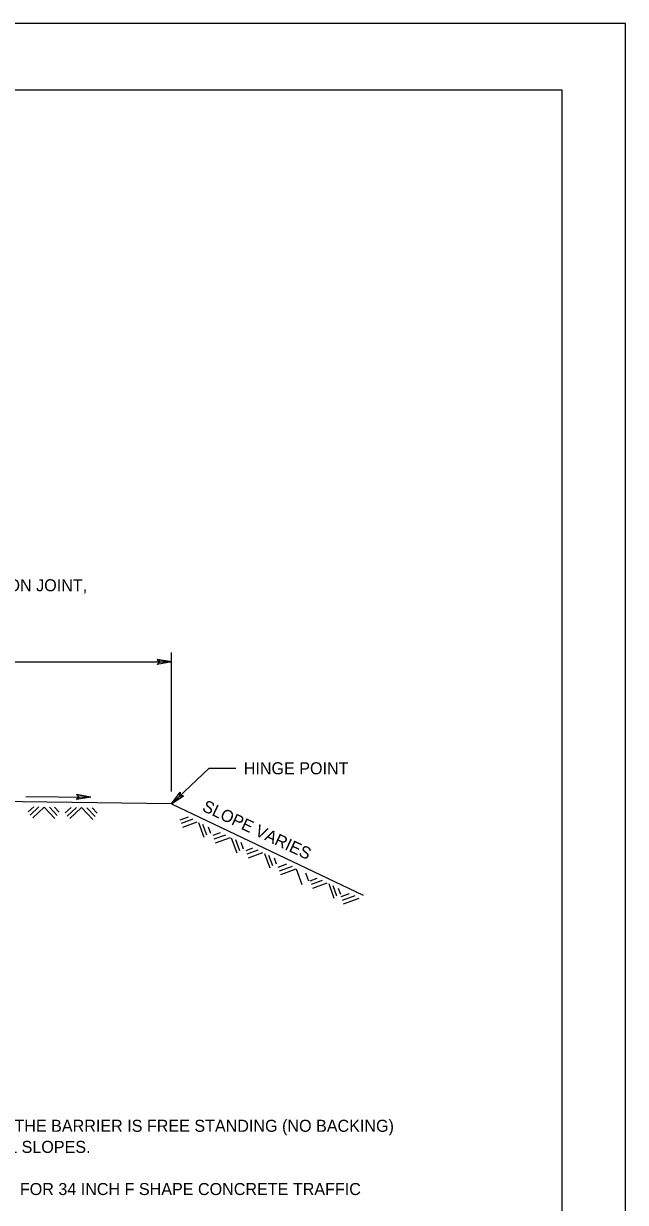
# Model space of a CAD drawing. Extents: x -32.9 to -15.8, y -6.5 to 4.5.
# Drawn here: x -18.82 to -15.82, y -1.37 to 4.5 of the extents above; entities that cross this region are included whole.
import ezdxf

# ---------------------------------------------------------------- set-up
doc = ezdxf.new("R2010")
doc.units = 0
for name, color, linetype in [('BORD-LINE', 7, 'Continuous'), ('DETL-DIMS', 7, 'Continuous'), ('Level 10', 7, 'Continuous'), ('Level 12', 7, 'Continuous'), ('Level 6', 7, 'Continuous'), ('SECT-GRND_P', 7, 'Continuous'), ('USER-CLIP', 7, 'Continuous')]:
    doc.layers.add(name, color=color, linetype=linetype)

msp = doc.modelspace()

# ---------------------------------------------------------------- linework, layer by layer
at = {"layer": 'BORD-LINE'}
msp.add_lwpolyline([(-23.5151, 4.1733), (-16.1409, 4.1733), (-16.1409, -6.1798), (-23.5151, -6.1798)], close=True, dxfattribs=at)
at = {"layer": 'DETL-DIMS'}
for p, q in [((-18.0854, 1.3241), (-18.1569, 1.3366)), ((-18.1569, 1.3366), (-18.1434, 1.3241)), ((-18.0854, 1.3241), (-18.1569, 1.3114)), ((-18.1434, 1.3241), (-18.1569, 1.3114)), ((-18.5445, 0.6509), (-18.5582, 0.6383)), ((-18.4865, 0.6502), (-18.5582, 0.6383)), ((-18.4865, 0.6502), (-18.5579, 0.6635)), ((-18.5579, 0.6635), (-18.5445, 0.6509)), ((-18.0854, 0.6164), (-18.0422, 0.6748)), ((-18.0854, 0.6164), (-18.0249, 0.6565)), ((-18.0433, 0.6563), (-18.0422, 0.6748)), ((-18.0249, 0.6565), (-18.0433, 0.6563))]:
    msp.add_line(p, q, dxfattribs=at)
for points in [[(-18.1569, 1.3366), (-18.0854, 1.3241), (-18.1569, 1.3114), (-18.1434, 1.3241)], [(-18.5579, 0.6635), (-18.4865, 0.6502), (-18.5582, 0.6383), (-18.5445, 0.6509)], [(-18.0249, 0.6565), (-18.0854, 0.6164), (-18.0422, 0.6748), (-18.0433, 0.6563)]]:
    msp.add_lwpolyline(points, close=True, dxfattribs=at)
at = {"layer": 'Level 10'}
for p, q in [((-18.0854, 0.6776), (-18.0854, 1.3714)), ((-20.0854, 1.3241), (-18.0854, 1.3241)), ((-17.8982, 0.794), (-18.0854, 0.6164)), ((-17.8982, 0.794), (-17.7654, 0.794)), ((-18.8108, 0.6539), (-18.4865, 0.6502))]:
    msp.add_line(p, q, dxfattribs=at)
at = {"layer": 'Level 6'}
for p, q in [((-18.7986, 0.5763), (-18.7716, 0.6016)), ((-18.7456, 0.6012), (-18.7886, 0.561)), ((-18.776, 0.548), (-18.7196, 0.6008)), ((-18.7196, 0.6008), (-18.6665, 0.5444)), ((-18.6548, 0.5594), (-18.6936, 0.6004)), ((-18.6676, 0.6001), (-18.6443, 0.5752)), ((-18.6143, 0.5715), (-18.5849, 0.5989)), ((-18.5589, 0.5985), (-18.6044, 0.556)), ((-18.5917, 0.5432), (-18.5329, 0.5981)), ((-18.5329, 0.5981), (-18.4778, 0.5394)), ((-18.466, 0.5544), (-18.5069, 0.5978)), ((-18.4809, 0.5974), (-18.4553, 0.5702)), ((-18.0415, 0.5379), (-18.0004, 0.5529)), ((-17.9792, 0.5398), (-18.037, 0.5188)), ((-18.0295, 0.5009), (-17.9567, 0.5274)), ((-17.95, 0.5244), (-17.9235, 0.4513)), ((-17.9089, 0.4609), (-17.9284, 0.5141)), ((-17.903, 0.5023), (-17.8914, 0.4701)), ((-17.8784, 0.4601), (-17.8419, 0.4734)), ((-17.8165, 0.4616), (-17.8739, 0.4408)), ((-17.8664, 0.4231), (-17.792, 0.4499)), ((-17.7875, 0.4478), (-17.7604, 0.3734)), ((-17.7455, 0.3829), (-17.7655, 0.4374)), ((-17.7404, 0.4256), (-17.728, 0.3921)), ((-17.7137, 0.3851), (-17.68, 0.3973)), ((-17.655, 0.3854), (-17.7092, 0.3658)), ((-17.7017, 0.3481), (-17.6304, 0.3739)), ((-17.6217, 0.3698), (-17.5957, 0.2984)), ((-17.581, 0.3079), (-17.5999, 0.3596)), ((-17.5745, 0.3478), (-17.5634, 0.3173)), ((-17.5532, 0.3014), (-17.5099, 0.3173)), ((-17.4845, 0.3054), (-17.5487, 0.2823)), ((-17.541, 0.2643), (-17.4635, 0.2926)), ((-17.4635, 0.2926), (-17.4352, 0.2148)), ((-17.4177, 0.2738), (-17.4029, 0.2336)), ((-17.3939, 0.2341), (-17.3597, 0.2466)), ((-17.3345, 0.2346), (-17.3892, 0.2148)), ((-17.3817, 0.1971), (-17.31, 0.2233)), ((-17.302, 0.2194), (-17.2759, 0.1474)), ((-17.261, 0.1569), (-17.28, 0.2091)), ((-17.2549, 0.1973), (-17.2435, 0.1663)), ((-17.2399, 0.1553), (-17.198, 0.1706)), ((-17.1727, 0.1586), (-17.2352, 0.1359)), ((-17.2279, 0.1181), (-17.1502, 0.1464))]:
    msp.add_line(p, q, dxfattribs=at)
at = {"layer": 'SECT-GRND_P'}
for q in [(-19.752, 0.6391), (-17.1312, 0.1619)]:
    msp.add_line((-18.0854, 0.6164), q, dxfattribs=at)
at = {"layer": 'USER-CLIP'}
msp.add_lwpolyline([(-15.824, 4.5033), (-24.324, 4.5033), (-24.324, -6.4967), (-15.824, -6.4967)], close=True, dxfattribs=at)

# ---------------------------------------------------------------- texts
at = {"layer": 'Level 12'}
for s, p in [('ROUGHEN CONSTRUCTION JOINT, ', (-19.8607, 1.6756)), ('HINGE POINT', (-17.7253, 0.764)), ('TO BE USED WHEN THE BARRIER IS FREE STANDING (NO BACKING)', (-19.6434, -1.0167)), ('AT THE TOP OF FILL SLOPES.', (-19.6434, -1.1217)), ('SEE STD. MD 648.45 FOR 34 INCH F SHAPE CONCRETE TRAFFIC ', (-19.6434, -1.3317))]:
    msp.add_text(s, height=0.06001, dxfattribs=at).set_placement(p)
msp.add_text('SLOPE VARIES', height=0.06001, rotation=335, dxfattribs=at).set_placement((-17.9368, 0.5839))

doc.saveas('drawing.dxf')
